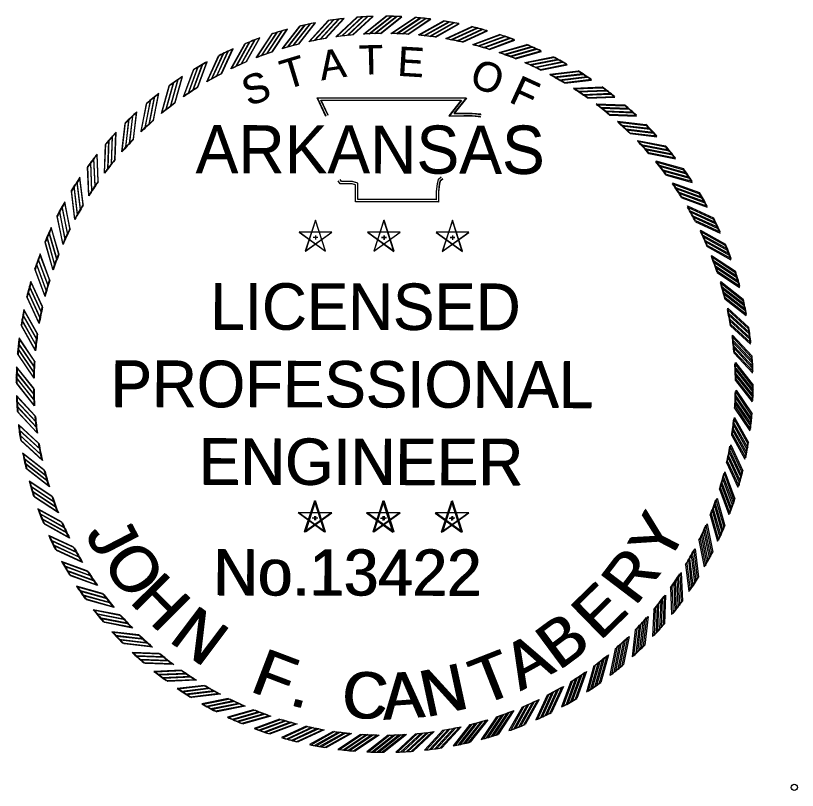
# Model space of a CAD drawing. Extents: x 8749 to 11879, y 13275 to 15339.
# Drawn here: x 11619.2 to 11876.6, y 13316.4 to 13571.7 of the extents above; entities that cross this region are included whole.
import ezdxf

# ---------------------------------------------------------------- set-up
doc = ezdxf.new("R2010")
doc.units = 0
doc.layers.add('Default', color=7, linetype='Continuous')
doc.layers.add('NO PLOT CELL', color=7, linetype='Continuous')

# ---------------------------------------------------------------- blocks, each defined once
blk = doc.blocks.new('STAR')
at = {"layer": 'Default'}
for p, q in [((-0.0001, 0.0615), (-0.0366, -0.0504)), ((0.0362, -0.0503), (0, 0.0617)), ((0.0587, 0.0188), (-0.059, 0.0189)), ((-0.0589, 0.0188), (0.0363, -0.0505)), ((-0.0365, -0.0503), (0.0589, 0.0188)), ((-0.0085, 0), (0.009, 0)), ((0, 0.0063), (0, -0.0085))]:
    blk.add_line(p, q, dxfattribs=at)
blk = doc.blocks.new('RP')
at = {"layer": 'Default'}
for p, q in [((-0.0781, 1.2656), (0.003, 1.33)), ((-0.058, 1.2667), (0.0216, 1.3299)), ((-0.0375, 1.2674), (0.0405, 1.3294)), ((-0.0176, 1.2679), (0.059, 1.3287))]:
    blk.add_line(p, q, dxfattribs=at)
for radius, start, end in [(1.33, 87.4562, 89.8699), (1.268, 90.7933, 93.5307)]:
    blk.add_arc((0, 0), radius, start, end, dxfattribs=at)

msp = doc.modelspace()

# ---------------------------------------------------------------- linework, layer by layer
at = {"layer": 'Default'}
for points in [[(11721.34, 13538.5), (11718.5, 13544.64), (11767.54, 13544.67), (11763.45, 13539.52), (11766.78, 13539.57), (11769.56, 13539.6), (11772.34, 13539.3)], [(11721.43, 13538.54), (11718.62, 13544.68), (11767.66, 13544.55), (11763.55, 13539.41), (11766.88, 13539.44), (11769.66, 13539.47), (11772.44, 13539.16)], [(11722.04, 13538.83), (11719.72, 13543.87), (11765.93, 13543.89), (11761.82, 13538.72), (11766.79, 13538.79), (11769.52, 13538.82), (11772.26, 13538.53)], [(11722.14, 13538.86), (11719.83, 13543.9), (11766.05, 13543.77), (11761.91, 13538.62), (11766.88, 13538.67), (11769.62, 13538.69), (11772.35, 13538.39)], [(11759.32, 13518.56), (11758.3, 13517.72), (11757.94, 13516.4), (11757.65, 13513.76), (11757.65, 13511.1), (11731.82, 13511.1), (11731.82, 13514.9), (11731.82, 13516.49), (11730.05, 13517.03), (11726.46, 13517.03), (11726, 13517.74)], [(11759.82, 13517.95), (11758.98, 13517.27), (11758.7, 13516.26), (11758.42, 13513.71), (11758.42, 13510.32), (11731.05, 13510.32), (11731.05, 13514.9), (11731.05, 13515.92), (11729.94, 13516.26), (11726.04, 13516.26), (11725.35, 13517.31)], [(11759.84, 13517.85), (11759, 13517.18), (11758.72, 13516.16), (11758.44, 13513.62), (11758.42, 13510.23), (11731.05, 13510.32), (11731.06, 13514.9), (11731.07, 13515.92), (11729.96, 13516.26), (11726.06, 13516.27), (11725.38, 13517.33)], [(11759.35, 13518.46), (11758.32, 13517.62), (11757.96, 13516.31), (11757.66, 13513.66), (11757.65, 13511.01), (11731.83, 13511.1), (11731.84, 13514.9), (11731.85, 13516.49), (11730.08, 13517.04), (11726.49, 13517.05), (11726.03, 13517.75)]]:
    msp.add_lwpolyline(points, dxfattribs=at)
at = {"layer": 'NO PLOT CELL'}
msp.add_circle((11875.61, 13317.43), 1, dxfattribs=at)

# ---------------------------------------------------------------- block references
at = {"layer": 'Default'}
for name, p, xscale, yscale, rotation in [('RP', (11740.82, 13450.26), 91.17655343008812, 91.17655343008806, 9.000000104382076), ('RP', (11740.61, 13450.23), 91.17655343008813, 91.17655343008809, 8.804199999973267), ('RP', (11740.82, 13450.26), 91.17655343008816, 91.1765534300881, 4.500000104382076), ('RP', (11740.61, 13450.23), 91.17655343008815, 91.17655343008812, 4.304199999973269), ('RP', (11740.82, 13450.26), 91.17655343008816, 91.1765534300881, 1.0438208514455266e-07), ('RP', (11740.61, 13450.23), 91.17655343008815, 91.1765534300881, -0.19580000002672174), ('RP', (11740.82, 13450.26), 91.17655343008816, 91.17655343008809, -4.499999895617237), ('RP', (11740.61, 13450.23), 91.17655343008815, 91.17655343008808, -4.695800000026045), ('RP', (11740.82, 13450.26), 91.17655343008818, 91.17655343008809, -8.999999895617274), ('RP', (11740.61, 13450.23), 91.17655343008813, 91.17655343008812, -9.19580000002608), ('RP', (11740.82, 13450.26), 91.17655343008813, 91.17655343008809, 13.500000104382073), ('RP', (11740.61, 13450.23), 91.17655343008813, 91.17655343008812, 13.304199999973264), ('RP', (11740.82, 13450.26), 91.17655343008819, 91.17655343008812, -13.499999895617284), ('RP', (11740.61, 13450.23), 91.17655343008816, 91.17655343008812, -13.695800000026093), ('RP', (11740.82, 13450.26), 91.17655343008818, 91.1765534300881, -17.99999989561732), ('RP', (11740.61, 13450.23), 91.17655343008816, 91.1765534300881, -18.195800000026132), ('RP', (11740.82, 13450.26), 91.17655343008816, 91.1765534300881, 18.00000010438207), ('RP', (11740.61, 13450.23), 91.17655343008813, 91.17655343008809, 17.80419999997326), ('RP', (11740.82, 13450.26), 91.17655343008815, 91.17655343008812, -22.499999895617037), ('RP', (11740.61, 13450.23), 91.17655343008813, 91.17655343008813, -22.695800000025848), ('RP', (11740.82, 13450.26), 91.17655343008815, 91.1765534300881, 22.50000010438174), ('RP', (11740.61, 13450.23), 91.17655343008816, 91.17655343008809, 22.304199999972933), ('RP', (11740.82, 13450.26), 91.17655343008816, 91.17655343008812, 27.00000010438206), ('RP', (11740.61, 13450.23), 91.17655343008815, 91.17655343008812, 26.80419999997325), ('RP', (11740.82, 13450.26), 91.17655343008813, 91.17655343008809, -26.999999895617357), ('RP', (11740.61, 13450.23), 91.17655343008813, 91.17655343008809, -27.19580000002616), ('RP', (11740.82, 13450.26), 91.17655343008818, 91.17655343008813, -31.49999989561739), ('RP', (11740.61, 13450.23), 91.17655343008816, 91.17655343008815, -31.695800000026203), ('RP', (11740.82, 13450.26), 91.1765534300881, 91.17655343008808, 31.500000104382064), ('RP', (11740.61, 13450.23), 91.17655343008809, 91.17655343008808, 31.30419999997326), ('RP', (11740.82, 13450.26), 91.17655343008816, 91.17655343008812, -35.99999989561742), ('RP', (11740.61, 13450.23), 91.17655343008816, 91.17655343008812, -36.195800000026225), ('RP', (11740.82, 13450.26), 91.17655343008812, 91.1765534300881, 36.00000010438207), ('RP', (11740.61, 13450.23), 91.1765534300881, 91.1765534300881, 35.804199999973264), ('RP', (11740.82, 13450.26), 91.17655343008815, 91.17655343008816, -40.499999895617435), ('RP', (11740.82, 13450.26), 91.17655343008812, 91.1765534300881, 40.50000010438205), ('RP', (11740.61, 13450.23), 91.17655343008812, 91.1765534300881, 40.30419999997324), ('RP', (11740.61, 13450.23), 91.17655343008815, 91.17655343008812, -40.69580000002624), ('RP', (11740.82, 13450.26), 91.17655343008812, 91.17655343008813, 45.00000010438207), ('RP', (11740.61, 13450.23), 91.17655343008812, 91.1765534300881, 44.80419999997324), ('RP', (11740.82, 13450.26), 91.17655343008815, 91.1765534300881, -44.99999989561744), ('RP', (11740.61, 13450.23), 91.17655343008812, 91.1765534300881, -45.19580000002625), ('RP', (11740.82, 13450.26), 91.1765534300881, 91.1765534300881, -49.499999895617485), ('RP', (11740.61, 13450.23), 91.1765534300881, 91.17655343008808, -49.695800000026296), ('RP', (11740.82, 13450.26), 91.17655343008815, 91.17655343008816, 49.500000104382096), ('RP', (11740.61, 13450.23), 91.17655343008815, 91.17655343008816, 49.30419999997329), ('RP', (11740.82, 13450.26), 91.17655343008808, 91.17655343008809, -53.999999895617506), ('RP', (11740.61, 13450.23), 91.17655343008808, 91.17655343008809, -54.1958000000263), ('RP', (11740.82, 13450.26), 91.17655343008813, 91.17655343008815, 54.00000010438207), ('RP', (11740.61, 13450.23), 91.17655343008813, 91.17655343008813, 53.804199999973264), ('RP', (11740.61, 13450.23), 91.1765534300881, 91.17655343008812, 58.304199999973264), ('RP', (11740.82, 13450.26), 91.1765534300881, 91.17655343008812, -58.49999989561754), ('RP', (11740.61, 13450.23), 91.17655343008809, 91.17655343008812, -58.69580000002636), ('RP', (11740.82, 13450.26), 91.1765534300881, 91.17655343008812, 58.50000010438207), ('RP', (11740.61, 13450.23), 91.17655343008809, 91.17655343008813, -63.19580000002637), ('RP', (11740.82, 13450.26), 91.17655343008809, 91.17655343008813, -62.999999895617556), ('RP', (11740.61, 13450.23), 91.17655343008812, 91.17655343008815, 62.804199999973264), ('RP', (11740.82, 13450.26), 91.17655343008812, 91.17655343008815, 63.000000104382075), ('STAR', (11717.88, 13498.72), 91.17655343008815, 91.1765534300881, -0.19580000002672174), ('STAR', (11717.92, 13498.68), 91.17655343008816, 91.1765534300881, 1.0438208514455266e-07), ('STAR', (11740.44, 13498.64), 91.17655343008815, 91.1765534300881, -0.19580000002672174), ('STAR', (11740.48, 13498.68), 91.17655343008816, 91.1765534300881, 1.0438208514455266e-07), ('STAR', (11762.99, 13498.57), 91.17655343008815, 91.1765534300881, -0.19580000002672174), ('STAR', (11763.03, 13498.68), 91.17655343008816, 91.1765534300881, 1.0438208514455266e-07), ('RP', (11740.82, 13450.26), 91.1765534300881, 91.17655343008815, -67.49999989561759), ('RP', (11740.61, 13450.23), 91.1765534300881, 91.17655343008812, 67.30419999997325), ('RP', (11740.82, 13450.26), 91.1765534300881, 91.17655343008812, 67.50000010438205), ('RP', (11740.61, 13450.23), 91.1765534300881, 91.17655343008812, -67.69580000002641), ('RP', (11740.61, 13450.23), 91.17655343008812, 91.17655343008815, 71.80419999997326), ('RP', (11740.82, 13450.26), 91.1765534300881, 91.17655343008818, 72.00000010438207), ('RP', (11740.61, 13450.23), 91.1765534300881, 91.17655343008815, -72.19580000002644), ('RP', (11740.82, 13450.26), 91.1765534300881, 91.17655343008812, -71.99999989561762), ('RP', (11740.61, 13450.23), 91.17655343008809, 91.17655343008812, -76.69580000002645), ('RP', (11740.82, 13450.26), 91.17655343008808, 91.1765534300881, -76.49999989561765), ('RP', (11740.61, 13450.23), 91.17655343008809, 91.17655343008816, 76.30419999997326), ('RP', (11740.82, 13450.26), 91.17655343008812, 91.17655343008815, 76.50000010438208), ('RP', (11740.61, 13450.23), 91.17655343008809, 91.17655343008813, 80.80419999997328), ('RP', (11740.61, 13450.23), 91.1765534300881, 91.17655343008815, -81.19580000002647), ('RP', (11740.82, 13450.26), 91.17655343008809, 91.17655343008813, -80.99999989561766), ('RP', (11740.82, 13450.26), 91.1765534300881, 91.17655343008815, 81.0000001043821), ('RP', (11740.61, 13450.23), 91.17655343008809, 91.17655343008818, 85.30419999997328), ('RP', (11740.82, 13450.26), 91.17655343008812, 91.17655343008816, 85.50000010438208), ('RP', (11740.61, 13450.23), 91.17655343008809, 91.17655343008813, -85.69580000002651), ('RP', (11740.82, 13450.26), 91.17655343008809, 91.17655343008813, -85.49999989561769), ('RP', (11740.61, 13450.23), 91.17655343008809, 91.17655343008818, -90.19580000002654), ('RP', (11740.82, 13450.26), 91.1765534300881, 91.17655343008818, -89.99999989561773), ('RP', (11740.61, 13450.23), 91.1765534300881, 91.17655343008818, 89.80419999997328), ('RP', (11740.82, 13450.26), 91.17655343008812, 91.17655343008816, 90.0000001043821), ('RP', (11740.61, 13450.23), 91.17655343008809, 91.17655343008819, 94.30419999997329), ('RP', (11740.82, 13450.26), 91.1765534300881, 91.1765534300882, 94.5000001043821), ('RP', (11740.61, 13450.23), 91.17655343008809, 91.17655343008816, -94.69580000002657), ('RP', (11740.82, 13450.26), 91.17655343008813, 91.17655343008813, -94.49999989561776), ('RP', (11740.61, 13450.23), 91.1765534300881, 91.17655343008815, -99.19580000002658), ('RP', (11740.82, 13450.26), 91.1765534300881, 91.17655343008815, -98.99999989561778), ('RP', (11740.61, 13450.23), 91.1765534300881, 91.17655343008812, 98.8041999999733), ('RP', (11740.82, 13450.26), 91.17655343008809, 91.17655343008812, 99.0000001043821), ('RP', (11740.61, 13450.23), 91.1765534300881, 91.17655343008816, 103.30419999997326), ('RP', (11740.82, 13450.26), 91.1765534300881, 91.17655343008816, 103.50000010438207), ('RP', (11740.61, 13450.23), 91.1765534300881, 91.17655343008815, -103.69580000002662), ('RP', (11740.82, 13450.26), 91.1765534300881, 91.17655343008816, -103.49999989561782), ('RP', (11740.61, 13450.23), 91.1765534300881, 91.17655343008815, -108.19580000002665), ('RP', (11740.82, 13450.26), 91.17655343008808, 91.17655343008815, -107.99999989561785), ('RP', (11740.61, 13450.23), 91.17655343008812, 91.17655343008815, 107.80419999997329), ('RP', (11740.82, 13450.26), 91.17655343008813, 91.17655343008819, 108.0000001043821), ('RP', (11740.61, 13450.23), 91.1765534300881, 91.17655343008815, 112.30419999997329), ('RP', (11740.82, 13450.26), 91.1765534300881, 91.17655343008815, 112.5000001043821), ('STAR', (11717.57, 13406.24), 91.17655343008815, 91.1765534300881, -0.19580000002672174), ('STAR', (11717.92, 13406.2), 91.17655343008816, 91.1765534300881, 1.0438208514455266e-07), ('STAR', (11740.12, 13406.16), 91.17655343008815, 91.1765534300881, -0.19580000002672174), ('STAR', (11740.48, 13406.2), 91.17655343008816, 91.1765534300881, 1.0438208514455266e-07), ('STAR', (11762.68, 13406.09), 91.17655343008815, 91.1765534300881, -0.19580000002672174), ('STAR', (11763.03, 13406.2), 91.17655343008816, 91.1765534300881, 1.0438208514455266e-07), ('RP', (11740.61, 13450.23), 91.1765534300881, 91.17655343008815, -112.69580000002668), ('RP', (11740.82, 13450.26), 91.17655343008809, 91.17655343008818, -112.49999989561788), ('RP', (11740.61, 13450.23), 91.17655343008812, 91.17655343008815, 116.80419999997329), ('RP', (11740.82, 13450.26), 91.17655343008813, 91.17655343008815, 117.0000001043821), ('RP', (11740.61, 13450.23), 91.17655343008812, 91.17655343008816, -117.19580000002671), ('RP', (11740.82, 13450.26), 91.17655343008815, 91.17655343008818, -116.9999998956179), ('RP', (11740.61, 13450.23), 91.17655343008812, 91.17655343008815, -121.69580000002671), ('RP', (11740.82, 13450.26), 91.17655343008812, 91.17655343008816, -121.4999998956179), ('RP', (11740.61, 13450.23), 91.17655343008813, 91.17655343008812, 121.30419999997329), ('RP', (11740.82, 13450.26), 91.17655343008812, 91.17655343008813, 121.5000001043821), ('RP', (11740.61, 13450.23), 91.17655343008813, 91.17655343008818, -126.19580000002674), ('RP', (11740.82, 13450.26), 91.17655343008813, 91.17655343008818, -125.99999989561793), ('RP', (11740.61, 13450.23), 91.17655343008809, 91.17655343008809, 125.80419999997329), ('RP', (11740.82, 13450.26), 91.17655343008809, 91.17655343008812, 126.00000010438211), ('RP', (11740.61, 13450.23), 91.1765534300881, 91.17655343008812, 130.3041999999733), ('RP', (11740.61, 13450.23), 91.1765534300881, 91.17655343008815, -130.6958000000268), ('RP', (11740.82, 13450.26), 91.17655343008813, 91.17655343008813, -130.49999989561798), ('RP', (11740.82, 13450.26), 91.17655343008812, 91.1765534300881, 130.50000010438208), ('RP', (11740.61, 13450.23), 91.17655343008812, 91.1765534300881, 134.80419999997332), ('RP', (11740.82, 13450.26), 91.17655343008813, 91.17655343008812, 135.00000010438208), ('RP', (11740.61, 13450.23), 91.17655343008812, 91.1765534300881, -135.19580000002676), ('RP', (11740.82, 13450.26), 91.17655343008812, 91.17655343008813, -134.99999989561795), ('RP', (11740.61, 13450.23), 91.1765534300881, 91.17655343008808, -139.69580000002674), ('RP', (11740.82, 13450.26), 91.17655343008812, 91.17655343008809, -139.49999989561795), ('RP', (11740.61, 13450.23), 91.17655343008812, 91.17655343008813, 139.30419999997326), ('RP', (11740.82, 13450.26), 91.17655343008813, 91.17655343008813, 139.50000010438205), ('RP', (11740.61, 13450.23), 91.17655343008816, 91.17655343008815, 143.8041999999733), ('RP', (11740.82, 13450.26), 91.17655343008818, 91.17655343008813, 144.00000010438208), ('RP', (11740.61, 13450.23), 91.17655343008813, 91.17655343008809, -144.19580000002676), ('RP', (11740.82, 13450.26), 91.17655343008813, 91.17655343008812, -143.99999989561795), ('RP', (11740.61, 13450.23), 91.17655343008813, 91.17655343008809, 148.3041999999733), ('RP', (11740.82, 13450.26), 91.17655343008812, 91.1765534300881, 148.50000010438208), ('RP', (11740.61, 13450.23), 91.1765534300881, 91.17655343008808, -148.69580000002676), ('RP', (11740.82, 13450.26), 91.1765534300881, 91.1765534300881, -148.49999989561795), ('RP', (11740.61, 13450.23), 91.17655343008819, 91.17655343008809, 152.8041999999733), ('RP', (11740.82, 13450.26), 91.17655343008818, 91.17655343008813, 153.00000010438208), ('RP', (11740.61, 13450.23), 91.17655343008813, 91.17655343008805, -153.1958000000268), ('RP', (11740.82, 13450.26), 91.17655343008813, 91.17655343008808, -152.99999989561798), ('RP', (11740.61, 13450.23), 91.17655343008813, 91.17655343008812, -157.6958000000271), ('RP', (11740.82, 13450.26), 91.17655343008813, 91.17655343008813, -157.4999998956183), ('RP', (11740.61, 13450.23), 91.17655343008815, 91.17655343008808, 157.3041999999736), ('RP', (11740.82, 13450.26), 91.17655343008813, 91.17655343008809, 157.50000010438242), ('RP', (11740.61, 13450.23), 91.17655343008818, 91.17655343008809, 161.8041999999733), ('RP', (11740.82, 13450.26), 91.17655343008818, 91.1765534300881, 162.00000010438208), ('RP', (11740.61, 13450.23), 91.17655343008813, 91.17655343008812, -162.19580000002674), ('RP', (11740.82, 13450.26), 91.17655343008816, 91.1765534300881, -161.99999989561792), ('RP', (11740.61, 13450.23), 91.17655343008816, 91.17655343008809, 166.3041999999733), ('RP', (11740.82, 13450.26), 91.17655343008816, 91.17655343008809, 166.50000010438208), ('RP', (11740.61, 13450.23), 91.17655343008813, 91.17655343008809, -166.69580000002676), ('RP', (11740.82, 13450.26), 91.17655343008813, 91.17655343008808, -166.49999989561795), ('RP', (11740.61, 13450.23), 91.17655343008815, 91.1765534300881, 170.8041999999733), ('RP', (11740.82, 13450.26), 91.17655343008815, 91.1765534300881, 171.00000010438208), ('RP', (11740.82, 13450.26), 91.17655343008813, 91.17655343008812, -175.49999989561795), ('RP', (11740.61, 13450.23), 91.1765534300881, 91.1765534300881, -171.19580000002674), ('RP', (11740.82, 13450.26), 91.17655343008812, 91.17655343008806, -170.99999989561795), ('RP', (11740.61, 13450.23), 91.17655343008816, 91.1765534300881, 175.3041999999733), ('RP', (11740.82, 13450.26), 91.17655343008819, 91.17655343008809, 175.50000010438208), ('RP', (11740.61, 13450.23), 91.17655343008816, 91.17655343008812, 179.8041999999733), ('RP', (11740.82, 13450.26), 91.17655343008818, 91.1765534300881, -179.99999989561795), ('RP', (11740.61, 13450.23), 91.17655343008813, 91.17655343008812, -175.69580000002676)]:
    msp.add_blockref(name, p, dxfattribs=dict(at, xscale=xscale, yscale=yscale, rotation=rotation))

# ---------------------------------------------------------------- texts
for s, height, rotation, p in [('A', 9.67, 8.6788, (11719.84, 13550.31)), ('A', 9.67, 8.483, (11719.98, 13550.35)), ('T', 9.67, 1.4789, (11732.33, 13552.23)), ('T', 9.67, 1.2831, (11732.48, 13552.23)), ('E', 9.67, 356.672, (11744.71, 13551.94)), ('E', 9.67, 356.4762, (11744.86, 13551.89)), ('T', 9.67, 16.9015, (11708.1, 13547.24)), ('T', 9.67, 16.7057, (11708.22, 13547.32)), ('O', 9.67, 341.2218, (11768.2, 13548.62)), ('O', 9.67, 341.026, (11768.33, 13548.5)), ('S', 9.67, 19.7726, (11695.79, 13541.72)), ('S', 9.67, 19.5768, (11695.9, 13541.84)), ('F', 9.67, 335.3628, (11781.24, 13543.53)), ('F', 9.67, 335.167, (11781.35, 13543.35)), ('ARKANSAS', 15.788, 0, (11678.41, 13519.72)), ('ARKANSAS', 15.788, 359.8042, (11678.45, 13519.9)), ('LICENSED', 15.285, 359.8042, (11683.17, 13468.34)), ('LICENSED', 15.285, 0, (11683.32, 13468.18)), ('PROFESSIONAL', 15.2848, 359.8042, (11650.33, 13442.89)), ('PROFESSIONAL', 15.2848, 0, (11650.56, 13442.62)), ('ENGINEER', 15.285, 359.8042, (11679.36, 13417.23)), ('ENGINEER', 15.285, 0, (11679.68, 13417.06)), ('Y', 15.28, 62.5392, (11833.79, 13390.24)), ('Y', 15.28, 62.735, (11834.2, 13390.59)), ('J', 15.28, 297.2813, (11641.81, 13401.1)), ('J', 15.28, 297.4771, (11642.18, 13400.8)), ('O', 15.28, 304.1899, (11647.22, 13391.73)), ('O', 15.28, 304.3857, (11647.63, 13391.44)), ('No.13422', 15.225, 359.8042, (11684.06, 13380.78)), ('No.13422', 15.225, 0, (11684.5, 13380.62)), ('R', 15.28, 52.7437, (11823.12, 13376.78)), ('R', 15.28, 52.9395, (11823.57, 13377.1)), ('H', 15.28, 314.7447, (11656.24, 13378.56)), ('H', 15.28, 314.9405, (11656.69, 13378.3)), ('E', 15.28, 44.306, (11811.47, 13365.41)), ('E', 15.28, 44.5018, (11811.97, 13365.68)), ('N', 15.28, 322.9417, (11669.15, 13365.78)), ('N', 15.28, 323.1375, (11669.64, 13365.57)), ('B', 15.28, 36.505, (11797.98, 13355.68)), ('B', 15.28, 36.7008, (11798.51, 13355.91)), ('A', 15.28, 28.8562, (11785.29, 13349.01)), ('A', 15.28, 29.052, (11785.84, 13349.19)), ('F', 15.28, 339.0288, (11695.83, 13349.23)), ('F', 15.28, 339.2246, (11696.38, 13349.11)), ('T', 15.28, 21.4329, (11772.58, 13344.23)), ('T', 15.28, 21.6287, (11773.15, 13344.37)), ('N', 15.28, 12.0703, (11754.14, 13340.42)), ('N', 15.28, 12.2661, (11754.72, 13340.5)), ('C', 15.28, 356.1028, (11726.15, 13340.65)), ('C', 15.28, 356.2986, (11726.73, 13340.63)), ('A', 15.28, 3.9092, (11740.17, 13339.63)), ('A', 15.28, 4.105, (11740.75, 13339.66)), ('.', 15.28, 344.7037, (11708.86, 13344.71)), ('.', 15.28, 344.8995, (11709.43, 13344.63))]:
    msp.add_text(s, height=height, rotation=rotation, dxfattribs=at).set_placement(p)

doc.saveas('drawing.dxf')
